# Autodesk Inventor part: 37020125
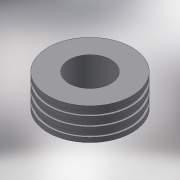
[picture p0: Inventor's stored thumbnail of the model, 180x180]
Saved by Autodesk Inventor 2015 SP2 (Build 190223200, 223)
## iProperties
Created: 2017-08
Part Number: 37020125
Material: Generic
Description: PLASSON MAN HOLE ADAPTOR 125
Document SubType Name: Modeling
Designer: Кирилл
Density: 1 g/cm^3
Appearance: Default
Author: Кирилл
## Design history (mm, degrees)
derived "37020-477207.ipt"
feature "Solid1::37020-477207.ipt"
tag "TaggingFeature1"
body "Solid1"
other parameters: "d0" = 135, "d1" = 235, "d2" = 223.25, "d3" = 111, "d4" = 125, "d6" = 39, "L_" = 135, "d_" = 125, "d_1" = 111, "D_" = 235, "H_" = 39
